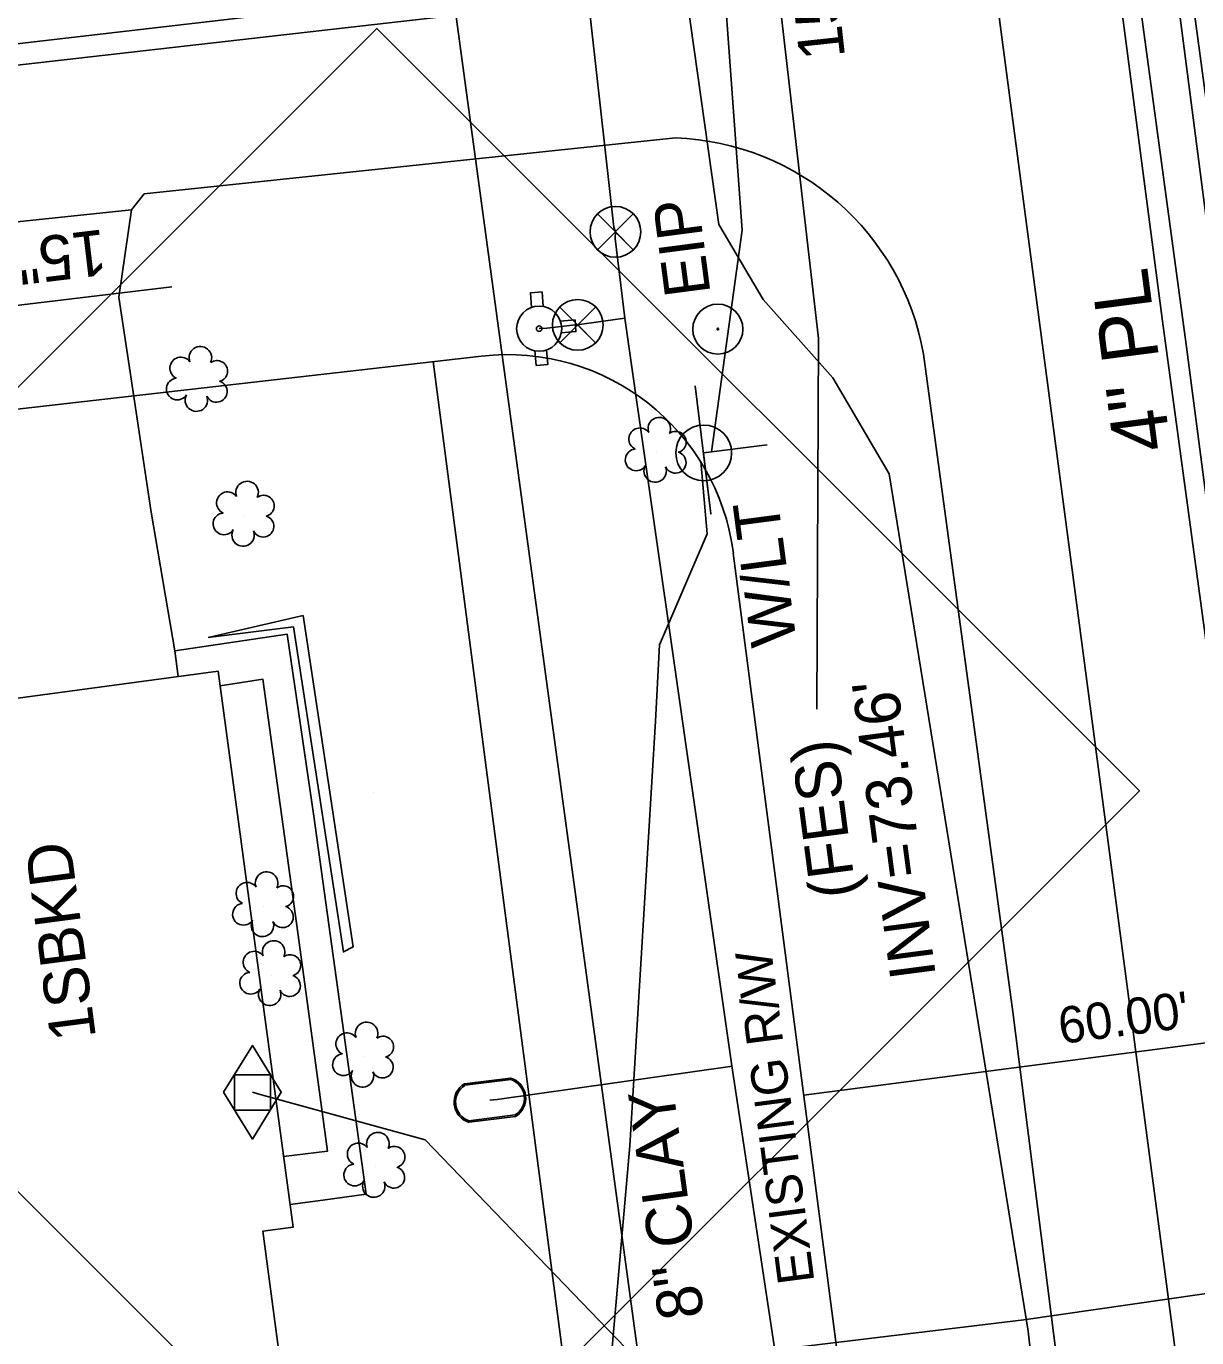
# Model space of a CAD drawing. Extents: x 2364404 to 2371833, y 798876 to 809754.
# Drawn here: x 2368483.8 to 2368586.6, y 806392.4 to 806507.5 of the extents above; entities that cross this region are included whole.
import ezdxf

# ---------------------------------------------------------------- set-up
doc = ezdxf.new("R2010")
doc.units = 0
for name, color, linetype in [('CTL Supplemental Horizontal and Vertical CELL', 7, 'Continuous'), ('Exist Building', 7, 'Continuous'), ('Exist Building Text', 7, 'Continuous'), ('Exist Horizontal Baseline Alignment Station Label', 7, 'Continuous'), ('Exist Other Culture Area Outline', 7, 'Continuous'), ('Exist Property Iron Pin CELL', 7, 'Continuous'), ('Exist Property Iron Pin Text', 7, 'Continuous'), ('Exist Right of Way Easement Line', 7, 'Continuous'), ('Exist Right of Way Line', 7, 'Continuous'), ('Exist Right of Way Line Text', 7, 'Continuous'), ('Exist Right of Way Width CELL', 7, 'Continuous'), ('Exist Roads EOP', 7, 'Continuous'), ('Exist Roads EOP Other', 7, 'Continuous'), ('Exist Structure Minor Pipes RCP 15 Inch', 7, 'Continuous'), ('Exist Structure Minor Pipes RCP 15 Inch Invert', 7, 'Continuous'), ('Exist Structure Minor Pipes RCP 15 Inch Leader', 7, 'Continuous'), ('Exist Structure Minor Pipes RCP 15 Inch Text', 7, 'Continuous'), ('Exist Utilities Gas Meter CELL', 7, 'Continuous'), ('Exist Utilities Gas UG Line SUE LOS B', 7, 'Continuous'), ('Exist Utilities Gas UG Line SUE LOS B Text', 7, 'Continuous'), ('Exist Utilities Power Joint Use Telephone CELL', 7, 'Continuous'), ('Exist Utilities Power Joint Use Telephone Text', 7, 'Continuous'), ('Exist Utilities Sanitary Sewer UG Line', 7, 'Continuous'), ('Exist Utilities Sanitary Sewer UG Line Text', 7, 'Continuous'), ('Exist Utilities Telephone UG Cable SUE LOS C', 7, 'Continuous'), ('Exist Utilities Telephone UG FO SUE LOS B', 7, 'Continuous'), ('Exist Utilities Telephone UG FO SUE LOS D', 7, 'Continuous'), ('Exist Utilities Water Fire Hydrant CELL', 7, 'Continuous'), ('Exist Utilities Water Meter CELL', 7, 'Continuous'), ('Exist Utilities Water UG Line SUE LOS B', 7, 'Continuous'), ('Exist Utilities Water Valve CELL', 7, 'Continuous'), ('Exist Vegetation Hedge Row', 7, 'Continuous'), ('Exist Vegetation Shrub CELL', 7, 'Continuous'), ('Prop Horizontal Alignment', 7, 'Continuous')]:
    doc.layers.add(name, color=color, linetype=linetype)

msp = doc.modelspace()

# ---------------------------------------------------------------- linework, layer by layer
at = {"layer": 'CTL Supplemental Horizontal and Vertical CELL'}
msp.add_line((2368514.3, 806440.27), (2368514.3, 806440.27), dxfattribs=at)
msp.add_lwpolyline([(2368447.81, 806440.5), (2368514.63, 806507.33), (2368581.57, 806440.39), (2368514.75, 806373.56)], close=True, dxfattribs=at)
at = {"layer": 'Exist Building'}
msp.add_lwpolyline([(2368500.68, 806450.89), (2368507.28, 806402.08), (2368504.6, 806401.72), (2368508.02, 806376.16), (2368475.85, 806371.86), (2368472.26, 806398.47), (2368474.02, 806398.7), (2368471.87, 806414.67), (2368469.98, 806414.42), (2368465.7, 806446.18)], close=True, dxfattribs=at)
at = {"layer": 'Exist Other Culture Area Outline'}
for points in [[(2368496.87, 806452.67), (2368506.75, 806454.14), (2368509.09, 806438.16), (2368513.69, 806404.96), (2368509.89, 806404.44), (2368507.01, 806404.06)], [(2368500.86, 806449.61), (2368504.62, 806450.19), (2368507.8, 806427.07), (2368510.29, 806408.75), (2368506.44, 806408.27)]]:
    msp.add_lwpolyline(points, dxfattribs=at)
at = {"layer": 'Exist Property Iron Pin CELL'}
for radius in [2.2, 0.0707]:
    msp.add_circle((2368544.56, 806480.93), radius, dxfattribs=at)
at = {"layer": 'Exist Right of Way Easement Line'}
msp.add_line((2368631.3, 805622.61), (2368519.57, 806478.09), dxfattribs=at)
at = {"layer": 'Exist Right of Way Line'}
for p, q in [((2368378.63, 806461.98), (2368523.82, 806478.56)), ((2368614.63, 805933.13), (2368545.92, 806461.27))]:
    msp.add_line(p, q, dxfattribs=at)
msp.add_arc((2368526.09, 806458.69), 20, 7.4124, 96.5171, dxfattribs=at)
at = {"layer": 'Exist Right of Way Width CELL'}
for p in [(2368611.61, 806421.42), (2368552.11, 806413.68)]:
    msp.add_line(p, (2368582.03, 806417.57), dxfattribs=at)
at = {"layer": 'Exist Roads EOP'}
for points in [[(2368605.64, 806313.93), (2368604.42, 806323.11), (2368599.43, 806362.08), (2368598.48, 806371.52), (2368591.5, 806423.47), (2368583.61, 806481.63), (2368579.42, 806513.66), (2368574.77, 806547.48), (2368569.37, 806590.17), (2368562.93, 806637.46), (2368555.74, 806690.75)], [(2368540.84, 806497.72), (2368494.2, 806492.81), (2368493.09, 806491.39), (2368470.71, 806489.05), (2368469.54, 806490), (2368425.78, 806484.58), (2368424.6, 806483.43), (2368402.38, 806481.15), (2368381.72, 806479.01), (2368373.86, 806478.14)], [(2368584.76, 806311.27), (2368583.62, 806321.27), (2368579.89, 806345.84), (2368578.54, 806347.72), (2368577.21, 806348.83), (2368575.07, 806364.95), (2368576.53, 806366.72), (2368577.12, 806368.52), (2368570.47, 806420.97), (2368562.62, 806478.73)]]:
    msp.add_lwpolyline(points, dxfattribs=at)
msp.add_arc((2368539.96, 806474.73), 23.01, 10.0087, 87.8045, dxfattribs=at)
at = {"layer": 'Exist Roads EOP Other'}
msp.add_lwpolyline([(2368493.09, 806491.39), (2368491.96, 806483.73), (2368492.96, 806477.16), (2368494.81, 806464.87), (2368496.87, 806452.67), (2368497.19, 806450.42)], dxfattribs=at)
at = {"layer": 'Exist Structure Minor Pipes RCP 15 Inch'}
for p, q in [((2368553.4, 806480.1), (2368546.19, 806542.8)), ((2368469.36, 806481.38), (2368496.62, 806484.64))]:
    msp.add_line(p, q, dxfattribs=at)
at = {"layer": 'Exist Structure Minor Pipes RCP 15 Inch Leader'}
msp.add_line((2368553.4, 806480.1), (2368553.24, 806447.55), dxfattribs=at)
at = {"layer": 'Exist Utilities Gas Meter CELL'}
msp.add_line((2368503.69, 806413.92), (2368503.69, 806413.92), dxfattribs=at)
for points in [[(2368501.16, 806413.92), (2368503.69, 806418.03), (2368506.23, 806413.92), (2368503.69, 806409.81), (2368501.16, 806413.92)], [(2368502.12, 806415.46), (2368505.27, 806415.46), (2368505.27, 806412.34), (2368502.12, 806412.34), (2368502.12, 806415.46)]]:
    msp.add_lwpolyline(points, dxfattribs=at)
at = {"layer": 'Exist Utilities Gas UG Line SUE LOS B'}
for points in [[(2368636, 806117.61), (2368624.85, 806183.15), (2368622.52, 806199.89), (2368621.61, 806209.68), (2368617.69, 806232.6), (2368610.43, 806288.73), (2368605.15, 806332.81), (2368596.39, 806397.55), (2368585.67, 806479.59), (2368578.75, 806530.79), (2368565.51, 806627.35), (2368559.18, 806675.74)], [(2368503.69, 806413.92), (2368504.16, 806413.77), (2368518.87, 806409.75), (2368537.97, 806389.91), (2368571.44, 806393.94), (2368596.39, 806397.55)]]:
    msp.add_lwpolyline(points, dxfattribs=at)
at = {"layer": 'Exist Utilities Power Joint Use Telephone CELL'}
msp.add_line((2368543.31, 806470.06), (2368543.31, 806470.06), dxfattribs=at)
msp.add_lwpolyline([(2368542.57, 806475.95), (2368543.95, 806464.7), (2368543.29, 806470.06), (2368548.89, 806470.76)], dxfattribs=at)
msp.add_circle((2368543.32, 806470.06), 2.45, dxfattribs=at)
at = {"layer": 'Exist Utilities Sanitary Sewer UG Line'}
for p, q in [((2368520.15, 806510.3), (2368179.13, 806470.56)), ((2368521.45, 806509.43), (2368565.1, 806188.32))]:
    msp.add_line(p, q, dxfattribs=at)
at = {"layer": 'Exist Utilities Telephone UG Cable SUE LOS C'}
for points in [[(2368562.41, 806326.14), (2368562.91, 806325.66), (2368570.86, 806328.91), (2368577.3, 806330.97), (2368578.51, 806333.4), (2368571.81, 806392.93), (2368559.61, 806468.23), (2368554.67, 806476.65), (2368548.55, 806483.54), (2368544.66, 806490.13), (2368539.66, 806525.45), (2368538.42, 806547.05), (2368539.61, 806549.62), (2368539.93, 806549.94)], [(2368544, 806470.16), (2368546.71, 806489.61), (2368544.04, 806526.12), (2368541.2, 806548.2), (2368539.93, 806549.94)], [(2368543.07, 806469.3), (2368543.61, 806462.95), (2368539.44, 806453.22), (2368539.08, 806446.5), (2368536.83, 806409.22), (2368535.08, 806389.19), (2368530.65, 806380.13), (2368524.44, 806373.75), (2368506.59, 806368.92), (2368485.39, 806373.34)]]:
    msp.add_lwpolyline(points, dxfattribs=at)
at = {"layer": 'Exist Utilities Telephone UG FO SUE LOS B'}
msp.add_lwpolyline([(2368679.23, 805789.16), (2368672.39, 805838.94), (2368666.32, 805886.94), (2368660.23, 805937.36), (2368653.43, 805985.89), (2368647.01, 806035.09), (2368643.66, 806085.34), (2368638.18, 806117.45), (2368626.73, 806183.23), (2368619.54, 806232.74), (2368612.29, 806288.8), (2368607.86, 806333.45), (2368599.32, 806397.89), (2368588.91, 806479.4), (2368582.51, 806528.6), (2368569.12, 806627.2), (2368562.57, 806675.96), (2368557.66, 806726.62)], dxfattribs=at)
at = {"layer": 'Exist Utilities Telephone UG FO SUE LOS D'}
msp.add_lwpolyline([(2368680.57, 805789.22), (2368673.06, 805838.98), (2368666.93, 805887.02), (2368660.99, 805937.49), (2368654.28, 805985.84), (2368647.84, 806035.01), (2368644.64, 806085.33), (2368638.99, 806117.57), (2368627.83, 806183.12), (2368620.23, 806232.81), (2368613.32, 806288.83), (2368608.65, 806333.46), (2368600.69, 806397.92), (2368590.34, 806479.53), (2368570.42, 806627.22), (2368563.79, 806676.05)], dxfattribs=at)
at = {"layer": 'Exist Utilities Water Fire Hydrant CELL'}
msp.add_line((2368528.87, 806480.97), (2368528.87, 806480.97), dxfattribs=at)
for points in [[(2368529.23, 806482.92), (2368529.13, 806484.2), (2368528.1, 806484.12), (2368528.21, 806482.82)], [(2368530.81, 806480.61), (2368532.1, 806480.71), (2368532.02, 806481.74), (2368530.73, 806481.63)], [(2368529.53, 806479.11), (2368529.63, 806477.82), (2368528.61, 806477.74), (2368528.5, 806479.05)]]:
    msp.add_lwpolyline(points, dxfattribs=at)
for radius in [1.98, 0.243]:
    msp.add_circle((2368528.87, 806480.97), radius, dxfattribs=at)
at = {"layer": 'Exist Utilities Water Meter CELL'}
msp.add_line((2368524.55, 806413.23), (2368524.55, 806413.23), dxfattribs=at)
for points in [[(2368522.32, 806414.66), (2368526.36, 806415.17)], [(2368522.34, 806414.53), (2368526.38, 806415.03)], [(2368526.77, 806411.93), (2368522.7, 806411.42)], [(2368526.79, 806411.79), (2368522.72, 806411.29)]]:
    msp.add_lwpolyline(points, dxfattribs=at)
for centre, radius, start, end in [((2368523.26, 806413.06), 1.86, 120.3119, 253.1132), ((2368525.84, 806413.39), 1.86, 300.7821, 73.4422), ((2368525.85, 806413.39), 1.73, 302.261, 72.0066), ((2368523.27, 806413.06), 1.73, 122.4348, 250.9162)]:
    msp.add_arc(centre, radius, start, end, dxfattribs=at)
at = {"layer": 'Exist Utilities Water UG Line SUE LOS B'}
for points in [[(2368591.16, 806087.23), (2368586.61, 806120.34), (2368584.18, 806145.32), (2368581.3, 806162.29), (2368574.92, 806210.1), (2368570.92, 806238.38), (2368570.73, 806239.93), (2368558.61, 806330.34), (2368551.92, 806375.78), (2368545.8, 806416.25), (2368536.4, 806481.89), (2368535.55, 806488.9), (2368535.57, 806489.47), (2368535.43, 806489.89), (2368531.58, 806524.39), (2368524.43, 806581.98), (2368519.2, 806620.08), (2368510.97, 806683.25)], [(2368528.87, 806480.97), (2368529.54, 806481.01), (2368531.8, 806481.27), (2368532.26, 806481.3), (2368532.61, 806481.35), (2368536.4, 806481.89)], [(2368524.55, 806413.23), (2368525.18, 806413.3), (2368545.84, 806416.2)]]:
    msp.add_lwpolyline(points, dxfattribs=at)
at = {"layer": 'Exist Utilities Water Valve CELL'}
for points in [[(2368537.14, 806491.04), (2368533.99, 806487.89), (2368535.57, 806489.47), (2368537.14, 806487.89), (2368533.99, 806491.04)], [(2368533.83, 806482.87), (2368530.68, 806479.72), (2368532.26, 806481.3), (2368533.83, 806479.72), (2368530.68, 806482.87)]]:
    msp.add_lwpolyline(points, dxfattribs=at)
for centre in [(2368535.57, 806489.47), (2368532.26, 806481.3)]:
    msp.add_circle(centre, 2.23, dxfattribs=at)
at = {"layer": 'Exist Vegetation Hedge Row'}
msp.add_lwpolyline([(2368499.8, 806453.85), (2368508.15, 806455.78), (2368512.53, 806426.68), (2368511.69, 806426.24), (2368507.3, 806454.79), (2368499.8, 806453.85)], dxfattribs=at)
at = {"layer": 'Exist Vegetation Shrub CELL'}
for p, q in [((2368498.9, 806476.37), (2368498.9, 806476.37)), ((2368539.19, 806470.15), (2368539.19, 806470.15)), ((2368503, 806464.54), (2368503, 806464.54)), ((2368504.71, 806430.25), (2368504.71, 806430.25)), ((2368505.34, 806424.2), (2368505.34, 806424.2)), ((2368513.49, 806417.04), (2368513.49, 806417.04)), ((2368514.48, 806407.37), (2368514.48, 806407.37))]:
    msp.add_line(p, q, dxfattribs=at)
for centre, radius, start, end in [((2368499.13, 806478.41), 0.99, 334.8391, 200.4717), ((2368497.42, 806477.5), 0.968, 35.8908, 245.4216), ((2368500.58, 806477.24), 0.929, 284.4567, 126.0861), ((2368497.1, 806475.67), 0.955, 95.1099, 327.9534), ((2368500.54, 806475.45), 0.937, 204.9913, 73.4601), ((2368498.77, 806474.69), 0.984, 151.2797, 21.387), ((2368537.71, 806471.28), 0.968, 35.8908, 245.4216), ((2368539.42, 806472.19), 0.99, 334.8391, 200.4717), ((2368540.86, 806471.02), 0.929, 284.4567, 126.0861), ((2368537.39, 806469.45), 0.955, 95.1099, 327.9534), ((2368540.83, 806469.22), 0.937, 204.9913, 73.4601), ((2368539.06, 806468.47), 0.984, 151.2797, 21.387), ((2368503.23, 806466.58), 0.99, 334.8391, 200.4717), ((2368501.52, 806465.67), 0.968, 35.8908, 245.4216), ((2368504.68, 806465.41), 0.929, 284.4567, 126.0861), ((2368501.2, 806463.83), 0.955, 95.1099, 327.9534), ((2368504.64, 806463.61), 0.937, 204.9913, 73.4601), ((2368502.88, 806462.85), 0.984, 151.2797, 21.387), ((2368504.94, 806432.29), 0.99, 334.8391, 200.4717), ((2368503.23, 806431.38), 0.968, 35.8908, 245.4216), ((2368506.38, 806431.12), 0.929, 284.4567, 126.0861), ((2368502.91, 806429.55), 0.955, 95.1099, 327.9534), ((2368506.35, 806429.32), 0.937, 204.9913, 73.4601), ((2368504.58, 806428.57), 0.984, 151.2797, 21.387), ((2368503.85, 806425.33), 0.968, 35.8908, 245.4216), ((2368505.56, 806426.24), 0.99, 334.8391, 200.4717), ((2368507.01, 806425.07), 0.929, 284.4567, 126.0861), ((2368503.54, 806423.5), 0.955, 95.1099, 327.9534), ((2368506.97, 806423.27), 0.937, 204.9913, 73.4601), ((2368505.21, 806422.52), 0.984, 151.2797, 21.387), ((2368513.72, 806419.09), 0.99, 334.8391, 200.4717), ((2368512, 806418.17), 0.968, 35.8908, 245.4216), ((2368515.16, 806417.91), 0.929, 284.4567, 126.0861), ((2368511.69, 806416.34), 0.955, 95.1099, 327.9534), ((2368515.12, 806416.12), 0.937, 204.9913, 73.4601), ((2368513.36, 806415.36), 0.984, 151.2797, 21.387), ((2368514.71, 806409.41), 0.99, 334.8391, 200.4717), ((2368513, 806408.49), 0.968, 35.8908, 245.4216), ((2368516.16, 806408.24), 0.929, 284.4567, 126.0861), ((2368512.68, 806406.66), 0.955, 95.1099, 327.9534), ((2368516.12, 806406.44), 0.937, 204.9913, 73.4601), ((2368514.35, 806405.68), 0.984, 151.2797, 21.387)]:
    msp.add_arc(centre, radius, start, end, dxfattribs=at)
at = {"layer": 'Prop Horizontal Alignment'}
for p, q in [((2368631.17, 806039.71), (2368556.15, 806607.59)), ((2368322.82, 806485.77), (2368568.53, 806513.87))]:
    msp.add_line(p, q, dxfattribs=at)

# ---------------------------------------------------------------- texts
at = {"layer": 'Exist Building Text'}
msp.add_text('1SBKD', height=4, rotation=97.4798, dxfattribs=at).set_placement((2368489.97, 806418.72))
at = {"layer": 'Exist Horizontal Baseline Alignment Station Label'}
msp.add_text('BL-110', height=73.5, rotation=97.4798, dxfattribs=at).set_placement((2368503.81, 806177.62))
at = {"layer": 'Exist Property Iron Pin Text'}
msp.add_text('EIP', height=4, rotation=97.4798, dxfattribs=at).set_placement((2368543.93, 806484.06))
at = {"layer": 'Exist Right of Way Line Text'}
msp.add_text('EXISTING R/W', height=3.2, rotation=97.4124, dxfattribs=at).set_placement((2368553.05, 806397.29))
at = {"layer": 'Exist Right of Way Width CELL'}
msp.add_text("60.00'", height=3.2, rotation=7.4124, dxfattribs=at).set_placement((2368574.67, 806418.15))
at = {"layer": 'Exist Structure Minor Pipes RCP 15 Inch Invert'}
for s, p in [("INV=73.46'", (2368563.71, 806424.13)), ('(FES)', (2368556.73, 806431.22))]:
    msp.add_text(s, height=4, rotation=97.4798, dxfattribs=at).set_placement(p)
at = {"layer": 'Exist Structure Minor Pipes RCP 15 Inch Text'}
for rotation, p in [(96.2295, (2368555.74, 806504.8)), (186.8167, (2368490.63, 806489.7))]:
    msp.add_text('15" RCP', height=4, rotation=rotation, dxfattribs=at).set_placement(p)
at = {"layer": 'Exist Utilities Gas UG Line SUE LOS B Text'}
msp.add_text('4" PL', height=5, rotation=97.4453, dxfattribs=at).set_placement((2368584.34, 806470.47))
at = {"layer": 'Exist Utilities Power Joint Use Telephone Text'}
msp.add_text('W/LT', height=4, rotation=97.4798, dxfattribs=at).set_placement((2368551.49, 806453.37))
at = {"layer": 'Exist Utilities Sanitary Sewer UG Line Text'}
msp.add_text('8" CLAY', height=4, rotation=97.7412, dxfattribs=at).set_placement((2368543.36, 806394.26))

doc.saveas('drawing.dxf')
